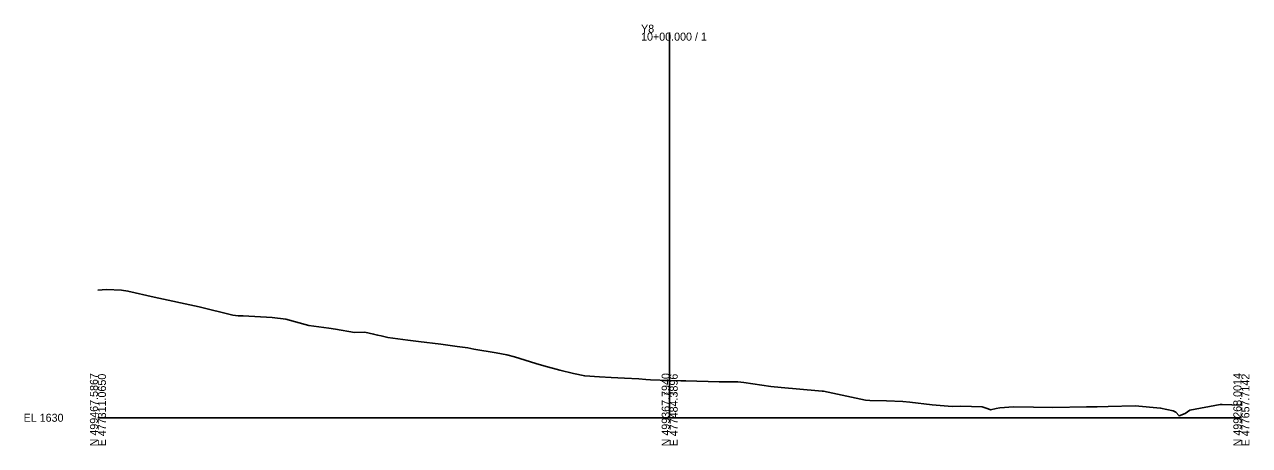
# Model space of a CAD drawing. Extents: x -26 to 403, y -10 to 2517.
# Drawn here: x -25.7 to 402.8, y -9.7 to 137.5 of the extents above; entities that cross this region are included whole.
import ezdxf

# ---------------------------------------------------------------- set-up
doc = ezdxf.new("R2010")
doc.units = 0
for name, color, linetype in [('Exist Cross Section Cell', 7, 'Continuous'), ('Exist XS Center Line Elevation Label', 7, 'Continuous'), ('Exist XS Ground Line', 7, 'Continuous')]:
    doc.layers.add(name, color=color, linetype=linetype)

msp = doc.modelspace()

# ---------------------------------------------------------------- linework, layer by layer
at = {"layer": 'Exist Cross Section Cell'}
for p, q in [((200, 0), (200, 134.63)), ((0, 0), (200, 0)), ((200, 0), (400, 0))]:
    msp.add_line(p, q, dxfattribs=at)
at = {"layer": 'Exist XS Ground Line'}
msp.add_lwpolyline([(0, 44.59), (2.94, 44.88), (8.26, 44.57), (10.49, 44.26), (19.61, 42.16), (35.43, 38.72), (47.19, 35.92), (49.08, 35.66), (50.78, 35.59), (60.9, 35.05), (65.73, 34.49), (73.79, 32.24), (80.79, 31.27), (83.1, 31.02), (89.8, 29.84), (93.32, 29.9), (96.43, 29.23), (97.82, 28.93), (99.07, 28.66), (99.54, 28.56), (101.42, 28.02), (108.41, 27.12), (112.14, 26.7), (119.95, 25.67), (125.72, 24.88), (129.38, 24.47), (131.5, 23.96), (139.34, 22.68), (143.04, 21.96), (145.76, 21.32), (153.22, 18.97), (155.95, 18.2), (161.58, 16.63), (166.31, 15.51), (170.27, 14.65), (175.5, 14.25), (179.57, 14.06), (184.2, 13.83), (189.22, 13.59), (191.63, 13.35), (193.27, 13.2), (200, 13.03), (203.95, 12.93), (204.5, 12.93), (205.7, 12.91), (217.28, 12.58), (223.83, 12.61), (225.94, 12.33), (235.37, 10.91), (239.05, 10.56), (252.08, 9.43), (253.39, 9.3), (253.77, 9.25), (268.55, 6.2), (269.99, 5.98), (275.87, 5.9), (281.53, 5.65), (283.96, 5.42), (291.87, 4.57), (297.37, 4), (298.94, 3.91), (301.91, 4.08), (309.36, 3.8), (311.4, 3.11), (312.24, 2.79), (314.18, 3.19), (315.46, 3.45), (320.25, 3.87), (327.27, 3.73), (334, 3.57), (345.87, 3.8), (349.58, 3.85), (353.45, 3.93), (362.88, 4.16), (371.74, 3.4), (376.14, 2.41), (377.02, 1.98), (378.22, 0.67), (380.39, 1.47), (381.95, 2.61), (392.62, 4.68), (393.22, 4.66), (400, 4.35)], dxfattribs=at)

# ---------------------------------------------------------------- texts
at = {"layer": 'Exist Cross Section Cell'}
for s, p in [('Y8', (190, 134.63)), ('10+00.000 / 1', (190, 131.83)), ('EL 1630', (-26, -1.4))]:
    msp.add_text(s, height=2.8, dxfattribs=at).set_placement(p)
for s, p in [('N 499467.5867', (0, -10)), ('E 477311.0650', (2.8, -10)), ('N 499367.7940', (200, -10)), ('E 477484.3896', (202.8, -10)), ('N 499268.0014', (400, -10)), ('E 477657.7142', (402.8, -10))]:
    msp.add_text(s, height=2.8, rotation=90, dxfattribs=at).set_placement(p)
at = {"layer": 'Exist XS Center Line Elevation Label'}
msp.add_text('1643.03', height=0.9, dxfattribs=at).set_placement((197.9, 8.13))

doc.saveas('drawing.dxf')
